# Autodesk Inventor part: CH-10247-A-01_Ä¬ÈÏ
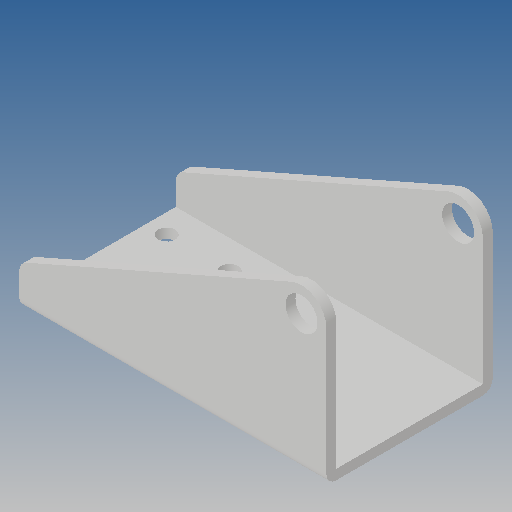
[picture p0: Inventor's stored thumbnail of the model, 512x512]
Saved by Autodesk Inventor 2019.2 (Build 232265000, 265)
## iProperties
Created: 2010-06
Part Number: CH-10247-A-01_Ä¬ÈÏ
Material: Ogólny
Document SubType Name: Modeling
Designer: CADENGINEERING4
Density: 1 g/cm^3
Appearance: Domyślna
Author: CADENGINEERING4
Revision Number: ÈÎºÎ
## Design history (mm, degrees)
feature "NONE"
node "Bryła1"
